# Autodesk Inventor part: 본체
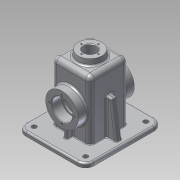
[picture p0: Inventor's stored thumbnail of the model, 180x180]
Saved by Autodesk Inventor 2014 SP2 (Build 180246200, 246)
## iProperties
Created: 2016-08
Part Number: 본체
Material: 알루미늄 6061
Document SubType Name: Modeling
Designer: user
Density: 2.71 g/cm^3
Appearance: 알루미늄 - 평지
Mass: 796.088 g
Surface Area: 911.213 cm^2
Volume: 293.76 cm^3
Author: user
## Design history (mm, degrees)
sketch "스케치1"
  geometry: L1 (-57.5, 65)-(57.5, 65); L2 (57.5, 65)-(57.5, -65); L3 (57.5, -65)-(-57.5, -65); L4 (-57.5, -65)-(-57.5, 65); L5 (-57.5, 65)-(57.5, -65); L6 (57.5, 65)-(-57.5, -65); 1 further point
  constraints: 12 end point, 2 midpoint, 2 parallel, 1 horizontal, 1 perpendicular
  dimensions: "d0" = 115 distance of L2.end L3.end; "d1" = 130 distance of L1.end L2.end
extrude "돌출1" new body sketch "스케치1" distance "d2" = 10; taper "d3" = 0 deg
node "작업 평면1"
sketch "스케치2"
  geometry: L1 (-32.5, -32.5)-(32.5, -32.5); L2 (32.5, -32.5)-(32.5, 32.5); L3 (32.5, 32.5)-(-32.5, 32.5); L4 (-32.5, 32.5)-(-32.5, -32.5); L5 (-32.5, -32.5)-(32.5, 32.5); L6 (32.5, -32.5)-(-32.5, 32.5); 1 further point
  constraints: 12 end point, 2 midpoint, 2 parallel, 1 horizontal, 1 perpendicular
  dimensions: "d5" = 65 distance of L3.end L2.end; "d6" = 65 distance of L2.end L1.end
extrude "돌출2" join sketch "스케치2" stored distance "d7" = 10; taper "d8" = 0 deg
sketch "스케치3"
  geometry: L1 (27.5, 27.5)-(-27.5, 27.5); L2 (-27.5, 27.5)-(-27.5, -27.5); L3 (-27.5, -27.5)-(27.5, -27.5); L4 (27.5, -27.5)-(27.5, 27.5); L5 (27.5, 27.5)-(-27.5, -27.5); L6 (-27.5, 27.5)-(27.5, -27.5); 1 further point
  constraints: 12 end point, 2 midpoint, 2 parallel, 1 horizontal, 1 perpendicular
  dimensions: "d9" = 55 distance of L3.end L2.end; "d10" = 55 distance of L2.end L1.end
extrude "돌출3" cut sketch "스케치3" distance "d11" = 105; taper "d12" = 0 deg
sketch "스케치4"
  geometry: L1 (-52.5, -60)-(52.5, -60); L2 (52.5, -60)-(52.5, 60); L3 (52.5, 60)-(-52.5, 60); L4 (-52.5, 60)-(-52.5, -60); L5 (-52.5, -60)-(52.5, 60); L6 (52.5, -60)-(-52.5, 60); L7 (57.5, -65)-(-57.5, -65) reference; L8 (57.5, 65)-(57.5, -65) reference; L9 (-57.5, 65)-(57.5, 65); L10 (57.5, 65)-(57.5, -65); L11 (57.5, -65)-(-57.5, -65); L12 (-57.5, -65)-(-57.5, 65); L13 (-57.5, 65)-(57.5, -65); L14 (57.5, 65)-(-57.5, -65); 1 further point
  constraints: 24 end point, 4 midpoint, 4 parallel, 2 horizontal, 2 perpendicular
  dimensions: "d13" = 105 distance of L3.end L2.end; "d14" = 120 distance of L2.end L1.end
extrude "돌출4" cut sketch "스케치4" distance "d15" = 3; taper "d16" = 0 deg
node "작업 평면3"
sketch "스케치8"
  geometry: L1 (27.5, 0)-(-27.5, 0) reference; C1 r 27.5 at (0, 55); 2 further points
  constraints: 1 centre point, 1 midpoint, 1 vertical alignment
  dimensions: "d41" = 55 diameter of C1; "d140" = 55 distance from line of C1.centre L1
extrude "돌출6" join sketch "스케치8" stored distance "d42" = 10; taper "d43" = 0 deg
hole "구멍3" diameter "d46" = 30; stored, may be unused: countersink angle "d50" = 90 deg, drill point angle "d52" = 0 deg; dims "d44" = 10, "d45" = 10, "d47" = 7, "d48" = 35, "d49" = 17, "d51" = 9
sketch "스케치9"
  geometry: L1 (21, 55)-(-21, 55); L2 (0, 76)-(0, 34); C1 r 27.5 at (0, 55) reference; A1 r 21 centre (0, 55) between (21, 55) and (-21, 55); 7 further points
  constraints: 7 coincident, 4 end point, 4 point on circle, 2 midpoint, 1 centre point, 1 horizontal, 1 perpendicular
  dimensions: "d53" = 42 diameter of A1
hole "구멍4" sketch "스케치9" at (0, 76), (21, 55), (0, 34), (-21, 55) diameter "d54" = 3.242; stored, may be unused: countersink angle "d58" = 90 deg, drill point angle "d60" = 118 deg; dims "d55" = 8, "d56" = 35, "d57" = 17, "d59" = 10
sketch "스케치10"
  geometry: L1 (65, 10)-(-65, 10) reference; L2 (-32.5, 110)-(-32.5, 10) reference; L3 (-47.5, 27.5)-(-32.5, 27.5) reference; L4 (-42.5, 10)-(-42.5, 27.5); L5 (-27.5, 0)-(-27.5, 105) reference; 2 further points
  constraints: 2 end point, 2 point on line, 1 perpendicular
  dimensions: "d61" = 15 distance between parallel lines of L4 L5
feature "리브1" sketch "스케치10" dims "d62" = 1, "d63" = 6, "d64" = 0, "d65" = 0, "d66" = 1, "d67" = 1
fillet "모깎기1" dims "d68" = 14
fillet "모깎기2" dims "d69" = 9
fillet "모깎기3" dims "d70" = 3
fillet "모깎기4" dims "d71" = 8
fillet "모깎기5" dims "d72" = 8
sketch "스케치11"
  geometry: L1 (43.5, 10)-(54.5, 10) reference; L2 (43.5, 10)-(-43.5, 10) reference; L3 (32.5, 10)-(32.5, 102) reference; L4 (57.5, 3)-(57.5, 7) reference; L5 (49.5, 10)-(41.068, 70); L6 (41.068, 70)-(32.5, 70); A1 r 3 centre (54.5, 7) between (57.5, 7) and (54.5, 10) reference; 1 further point
  constraints: 4 end point, 2 point on line, 1 perpendicular
  dimensions: "d73" = 8 deg angle of L5 L4; "d74" = 8 distance from line of L5.start L4; "d75" = 70 vertical distance of L5.end point (0, 0)
feature "리브2" sketch "스케치11" dims "d76" = 1, "d77" = 10, "d78" = 0, "d79" = 0, "d80" = 1, "d81" = 1
hole "구멍5" diameter "d84" = 8; stored, may be unused: countersink angle "d88" = 90 deg, drill point angle "d90" = 118 deg; dims "d82" = 10, "d83" = 10, "d85" = 8, "d86" = 35, "d87" = 17, "d89" = 10
hole "구멍6" diameter "d93" = 8; stored, may be unused: countersink angle "d97" = 90 deg, drill point angle "d99" = 118 deg; dims "d91" = 10, "d92" = 10, "d94" = 8, "d95" = 35, "d96" = 17, "d98" = 10
hole "구멍7" diameter "d102" = 8; stored, may be unused: countersink angle "d106" = 90 deg, drill point angle "d108" = 118 deg; dims "d100" = 10, "d101" = 10, "d103" = 8, "d104" = 35, "d105" = 17, "d107" = 10
hole "구멍8" diameter "d111" = 8; stored, may be unused: countersink angle "d115" = 90 deg, drill point angle "d117" = 118 deg; dims "d109" = 10, "d110" = 10, "d112" = 8, "d113" = 35, "d114" = 17, "d116" = 10
fillet "모깎기6" dims "d118" = 3
fillet "모깎기7" dims "d119" = 3
fillet "모깎기8" dims "d120" = 3
fillet "모깎기9" dims "d122" = 3
fillet "모깎기10" dims "d123" = 3
fillet "모깎기11" dims "d124" = 1
fillet "모깎기12" dims "d125" = 3
chamfer "모따기1" distance "d127" = 1; stored, may be unused: second distance "d128" = 2, angle "d129" = 45 deg
fillet "모깎기14" dims "d133" = 0.3
fillet "모깎기15" dims "d134" = 3
fillet "모깎기16" dims "d135" = 3
sketch "스케치12"
  geometry: L1 (43.272, -18)-(5.728, -18) reference; L2 (57, 0)-(57, 91) reference; 2 further points
  constraints: 1 other
  dimensions: "d136" = 26 distance from line of L1 point (24.5, 8); "d137" = 32.5 distance from line of point (24.5, 8) L2
feature "엠보싱1" sketch "스케치12" dims "d138" = 0.5, "d139" = 0
node "작업 평면4"
sketch "스케치13"
  geometry: C1 r 20 at (0, 0); 1 further point
  constraints: 1 centre point, 1 coincident
  dimensions: "d142" = 40 diameter of C1
extrude "돌출7" join sketch "스케치13" stored distance "d143" = 10; taper "d144" = 7 deg
hole "구멍9" diameter "d147" = 21; stored, may be unused: countersink angle "d151" = 90 deg, drill point angle "d153" = 118 deg; dims "d145" = 10, "d146" = 10, "d148" = 8, "d149" = 35, "d150" = 17, "d152" = 10
chamfer "모따기3" distance "d154" = 1; stored, may be unused: second distance "d155" = 2, angle "d156" = 45 deg
sketch "스케치14"
  geometry: L1 (0, -14.5)-(0, 14.5); L2 (-14.5, 0)-(14.5, 0); A1 r 14.5 centre (0, 0) between (0, -14.5) and (0, 14.5); 6 further points
  constraints: 6 coincident, 4 end point, 4 point on circle, 2 midpoint, 1 centre point, 1 perpendicular, 1 vertical
  dimensions: "d157" = 29 diameter of A1
hole "구멍10" sketch "스케치14" at (-14.5, 0), (0, -14.5), (0, 14.5), (14.5, 0) diameter "d158" = 2.459; stored, may be unused: countersink angle "d162" = 90 deg, drill point angle "d164" = 118 deg; dims "d159" = 7, "d160" = 35, "d161" = 17, "d163" = 9
fillet "모깎기17" dims "d165" = 3
node "솔리드1"
mirror "대칭1"
mirror "대칭2"
other parameters: "d39" = -47.5
